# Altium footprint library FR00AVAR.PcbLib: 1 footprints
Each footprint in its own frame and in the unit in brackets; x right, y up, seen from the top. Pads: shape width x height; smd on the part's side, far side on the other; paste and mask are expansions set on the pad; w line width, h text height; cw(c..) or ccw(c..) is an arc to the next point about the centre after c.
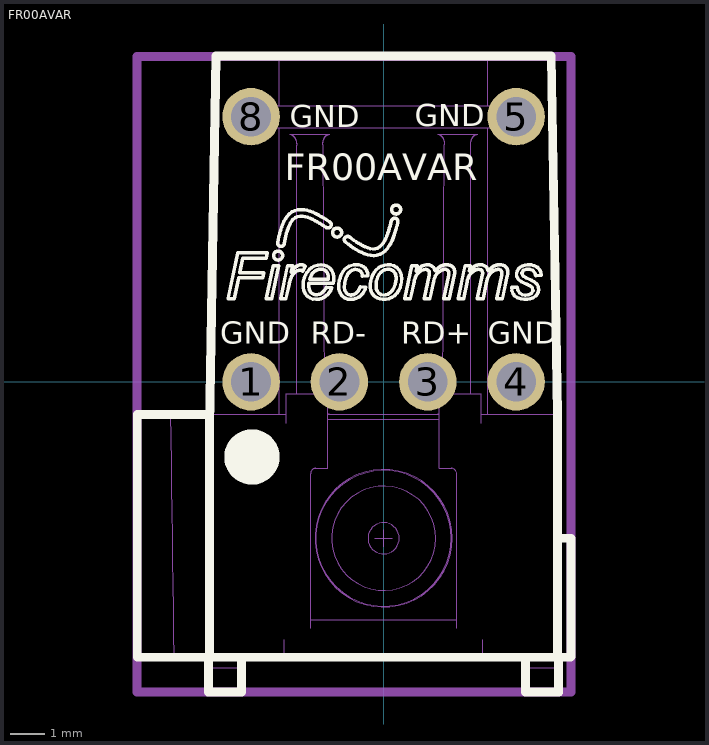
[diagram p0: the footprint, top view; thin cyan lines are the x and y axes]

## FR00AVAR [mil] "RedLink® Analogue Receiver Vertical Package"
height 744.09
pads (6):
  round 65 hole 45: 1(-150,0) 2(-50,0) 3(50,0) 4(150,0) 5(150,300) 8(-150,300)
Top Overlay:
  drawing of 818 lines, arcs and shapes, not listed
  text "FR00AVAR" at -112,228 h30
  text "GND" at -106,288 h25
  text "GND" at 35,289 h25
  text "GND" at -185.04,43.31 h25
  text "RD-" at -82.68,43.31 h25
  text "RD+" at 19.68,43.31 h25
  text "GND" at 118.11,43.31 h25
Mechanical 2:
  lines w10: -279,-351 212,-351 212,368 -279,368 -279,-351
Mechanical 19:
  drawing of 829 lines, arcs and shapes, not listed
3D body "Vertical Redlink Connector.stp": height 745.89, standoff -128.11, extent -278.74,-354.01 211.81,365.67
